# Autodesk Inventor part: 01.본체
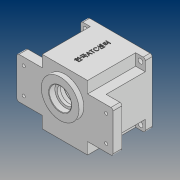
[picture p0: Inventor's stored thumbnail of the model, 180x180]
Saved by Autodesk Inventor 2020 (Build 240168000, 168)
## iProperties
Created: 2020-07
Part Number: 01.본체
Material: 일반
Document SubType Name: Modeling
Designer: PC312-
Density: 1 g/cm^3
Appearance: 기본값
Author: PC312-
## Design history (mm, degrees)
sketch "스케치1"
  geometry: L1 (-47, -47)-(47, -47); L2 (47, -47)-(47, 47); L3 (47, 47)-(-47, 47); L4 (-47, 47)-(-47, -47); L5 (-47, -47)-(47, 47); L6 (47, -47)-(-47, 47); 1 further point
  constraints: 12 end point, 2 midpoint, 2 parallel, 1 horizontal, 1 perpendicular
  dimensions: "d0" = 94 distance of L3.end L2.end; "d1" = 94 distance of L2.end L1.end
extrude "돌출1" new body sketch "스케치1" distance "d2" = 80; taper "d3" = 0 deg
sketch "스케치2"
  geometry: L1 (47, 47)-(-47, 47) reference; L2 (-47, -47)-(47, -47) reference; L3 (-33, 47)-(33, 47); L4 (33, 47)-(33, -47); L5 (33, -47)-(-33, -47); L6 (-33, -47)-(-33, 47); L7 (-47, 47)-(-47, -47) reference; L8 (47, -47)-(47, 47) reference; L9 (-47, 30)-(47, 30); L10 (47, 30)-(47, -30); L11 (47, -30)-(-47, -30); L12 (-47, -30)-(-47, 30); L13 (47, -47)-(47, 47) reference; L14 (33, 47)-(47, 47); 6 further points
  constraints: 18 end point, 4 parallel, 4 point on line, 3 horizontal, 2 perpendicular
  dimensions: "d4" = 33 distance from line of point (0, 0) L4; "d5" = 33 distance from line of point (0, 0) L6; "d6" = 30 distance from line of point (0, 0) L9; "d7" = 30 distance from line of point (0, 0) L11
extrude "돌출2" cut sketch "스케치2" distance "d8" = 70; taper "d9" = 0 deg
sketch "스케치3"
  geometry: L1 (47, -47)-(47, 47) reference; L2 (47, 47)-(33, 47); L3 (33, 47)-(33, 30); L4 (33, 30)-(47, 30); L5 (47, 30)-(47, 47); 2 further points
  constraints: 8 end point, 2 parallel, 1 horizontal, 1 perpendicular
  dimensions: "d10" = 30 distance from line of point (0, 0) L4; "d11" = 33 distance from line of point (0, 0) L3
extrude "돌출3" cut sketch "스케치3" distance "d12" = 70; taper "d13" = 0 deg
sketch "스케치4"
  geometry: L1 (-70, -30)-(70, -30); L2 (70, -30)-(70, 30); L3 (70, 30)-(-70, 30); L4 (-70, 30)-(-70, -30); L5 (-70, -30)-(70, 30); L6 (70, -30)-(-70, 30); 1 further point
  constraints: 12 end point, 2 midpoint, 2 parallel, 1 horizontal, 1 perpendicular
  dimensions: "d14" = 140 distance of L3.end L2.end; "d15" = 60 distance of L2.end L1.end
extrude "돌출4" join sketch "스케치4" distance "d16" = 13; taper "d17" = 0 deg
sketch "스케치5"
  geometry: C1 r 3.5 at (40, 40); 1 further point
  constraints: 1 centre point
  dimensions: "d18" = 7 diameter of C1; "d19" = 40 horizontal distance of point (0, 0) C1.centre; "d20" = 40 horizontal distance of point (0, 0) C1.centre
extrude "돌출5" cut sketch "스케치5" distance "d21" = 70; taper "d22" = 0 deg
sketch "스케치6"
  geometry: 3 further points
  dimensions: "d23" = 60 horizontal distance of point (0, 0) point (60, 19); "d24" = 19 vertical distance of point (0, 0) point (60, 19); "d25" = 60 horizontal distance of point (0, 0) point (60, -19); "d26" = 19 vertical distance of point (0, 0) point (60, -19)
hole "구멍1" sketch "스케치6" at (60, 19), (60, -19) diameter "d27" = 4.5; stored, may be unused: countersink angle "d31" = 90 deg, drill point angle "d33" = 118 deg; dims "d28" = 8, "d29" = 10, "d30" = 5, "d32" = 10
sketch "스케치7"
  geometry: C1 r 27.5 at (0, 11); 1 further point
  constraints: 1 centre point, 1 vertical alignment
  dimensions: "d34" = 55 diameter of C1; "d35" = 11 distance of point (0, 0) C1.centre
extrude "돌출6" join sketch "스케치7" distance "d36" = 7; taper "d37" = 0 deg
sketch "스케치8"
  geometry: C1 r 43 at (0, 0); 1 further point
  constraints: 1 centre point, 1 coincident
  dimensions: "d38" = 86 diameter of C1
extrude "돌출7" cut sketch "스케치8" distance "d39" = 9; taper "d40" = 0 deg
sketch "스케치9"
  geometry: C1 r 40 at (0, 0); 1 further point
  constraints: 1 centre point, 1 coincident
  dimensions: "d41" = 80 diameter of C1
extrude "돌출8" cut sketch "스케치9" distance "d42" = 62; taper "d43" = 0 deg
sketch "스케치10"
  geometry: C1 r 27.5 at (0, 11) reference; A1 r 21 centre (0, 11) between (8.978, -7.984) and (-8.978, -7.984); A2 r 15 centre (0, -20) between (-8.978, -7.984) and (8.978, -7.984); 1 further point
  constraints: 4 point on circle, 2 centre point, 1 coincident, 1 vertical alignment
  dimensions: "d44" = 42 diameter of A1; "d45" = 30 diameter of A2; "d46" = 20 distance of A2.centre point (0, 0)
extrude "돌출9" join sketch "스케치10" distance "d47" = 7; taper "d48" = 0 deg
sketch "스케치11"
  geometry: C1 r 12.5 at (0, 11); A1 r 21 centre (0, 11) between (8.978, -7.984) and (-8.978, -7.984) reference; 1 further point
  constraints: 1 centre point, 1 coincident
  dimensions: "d49" = 25 diameter of C1
extrude "돌출10" cut sketch "스케치11" extent not by distance; stored distance "d50" = 0; taper "d51" = 0 deg
sketch "스케치12"
  geometry: C1 r 12.5 at (0, 11) reference; C2 r 17.5 at (0, 11); 1 further point
  constraints: 1 centre point, 1 coincident
  dimensions: "d52" = 35 diameter of C2
extrude "돌출11" cut sketch "스케치12" distance "d53" = 10; taper "d54" = 0 deg
sketch "스케치13"
  geometry: C1 r 27.5 at (0, 0) reference; C2 r 16 at (0, 0); 1 further point
  constraints: 1 centre point, 1 coincident
  dimensions: "d55" = 32 diameter of C2
extrude "돌출12" cut sketch "스케치13" distance "d56" = 8.3; taper "d57" = 0 deg
chamfer "모따기2" distance "d61" = 1; stored, may be unused: second distance "d62" = 2, angle "d63" = 45 deg
sketch "스케치14"
  geometry: C1 r 11 at (0, -20); A1 r 15 centre (0, -20) between (-8.978, -7.984) and (8.978, -7.984) reference; 1 further point
  constraints: 1 centre point, 1 coincident
  dimensions: "d64" = 22 diameter of C1
extrude "돌출13" cut sketch "스케치14" distance "d65" = 7; taper "d66" = 0 deg
sketch "스케치15"
  geometry: C1 r 11 at (0, 0) reference; C2 r 9.5 at (0, 0); 1 further point
  constraints: 1 centre point, 1 coincident
  dimensions: "d67" = 19 diameter of C2
extrude "돌출14" cut sketch "스케치15" distance "d68" = 3; taper "d69" = 0 deg
fillet "모깎기1" dims "d70" = 3
chamfer "모따기3" distance "d71" = 1; stored, may be unused: second distance "d72" = 2, angle "d73" = 45 deg
sketch "스케치19" dims "d90" = 72
  geometry: L1 (-98, 0)-(98, 0) reference; L2 (-36, 4)-(-39.799, 4); L3 (-36, -4)-(-39.799, -4); A1 r 4 centre (-36, 0) between (-36, 4) and (-36, -4); A2 r 40 centre (0, 0) between (-39.799, 4) and (-39.799, -4) reference; 2 further points
  constraints: 4 end point, 4 point on circle, 2 tangent, 1 centre point, 1 coincident, 1 horizontal, 1 horizontal alignment, 1 parallel, 1 point on line, 2 other
  dimensions: "d91" = 8 diameter of A1
extrude "돌출17" join sketch "스케치19" stored distance "d92" = 3; taper "d93" = 0 deg
fillet "모깎기2" dims "d94" = 3
sketch "스케치20"
  geometry: A1 r 4 centre (-36, 0) between (-36, -4) and (-36, 4) reference; 2 further points
  constraints: 1 coincident
hole "구멍3" sketch "스케치20" at (-36, 0) diameter "d95" = 3.242; stored, may be unused: countersink angle "d99" = 90 deg, drill point angle "d101" = 118 deg; dims "d96" = 7, "d97" = 10, "d98" = 5, "d100" = 9
fillet "모깎기3" dims "d102" = 3
fillet "모깎기4" dims "d103" = 3
node "작업 평면1"
sketch "스케치21"
  geometry: L1 (77, 80)-(-11, 80) reference; 2 further points
  constraints: 1 vertical alignment, 1 other
  dimensions: "d105" = 40 distance from line of L1 point (33, 40)
feature "엠보싱1" sketch "스케치21" dims "d6" = 30, "d7" = 30, "d106" = 0.5, "d107" = 0
chamfer "모따기4" distance "d108" = 0.8; stored, may be unused: second distance "d109" = 2, angle "d110" = 30 deg
node "솔리드1"
mirror "미러1"
mirror "미러2"
mirror "미러3"
mirror "미러4"
node "투영된 루프1"
feature "A9D066F2-1C7D-4E18-AEED-F7BC21143FA4" dims "d27" = 4.5, "d28" = 8, "d29" = 10, "d30" = 5, "d31" = 90 deg, "d32" = 10, "d33" = 118 deg
